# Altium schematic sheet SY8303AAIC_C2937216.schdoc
size 127 x 101 mm
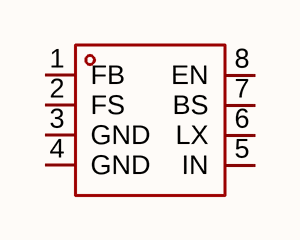
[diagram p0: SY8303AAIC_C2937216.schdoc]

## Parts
U?  sy8303aaic_c2937216  [TSOT-23-8_L2.9-W1.6-P0.65-LS2.8-BR]  (value not drawn)

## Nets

Not connected (* = marked no-connect by the designer): U? 1(FB) 2(FS) 3(GND) 4(GND) 5(IN) 6(LX) 7(BS) 8(EN)

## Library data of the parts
U? = sy8303aaic_c2937216: 功能类型:降压型;工作电压:4.5V~40V;输出电压:-;输出电流:3A;输出类型:可调;; Manufacturer: Silergy(矽力杰); AddInBom: yes; ModelId: a4a866e84c1d4e21a00dbb6d6e7ebbb6; ModelTransform: 110.45568,114.173,0,180,0,0,0,0,0; Function: 降压型; Output Current: 3A; Frequency - Switching: 500kHz~2.5MHz; Synchronous Rectifier: 是; Number of Outputs: 1; Topology: 降压式; Quiescent Current: 19uA; Switch tube (built-in/external): 内置; Output Type: 可调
